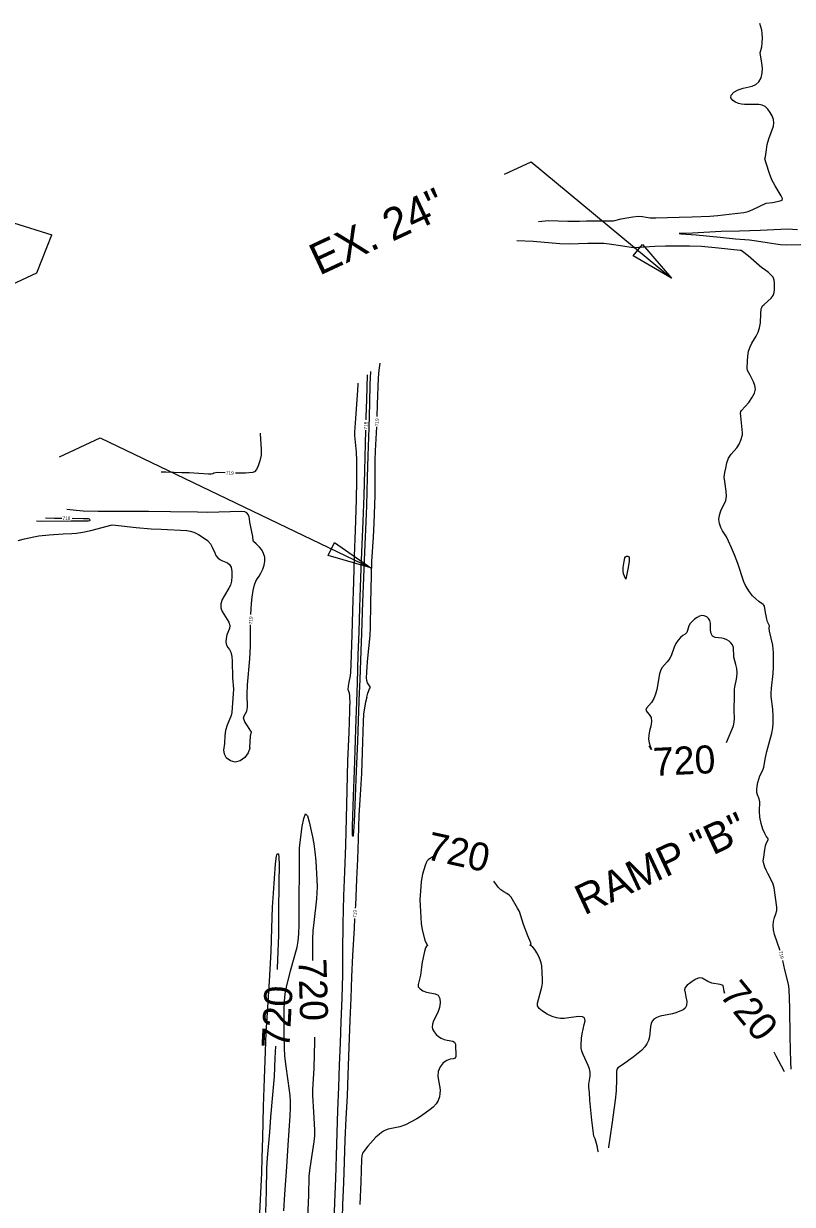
# Model space of a CAD drawing. Extents: x -310467766 to 17062430, y -322263100 to 8322522.
# Drawn here: x 1394051 to 1394957, y 571443 to 572834 of the extents above; entities that cross this region are included whole.
import ezdxf

# ---------------------------------------------------------------- set-up
doc = ezdxf.new("R2010")
doc.units = 0
for name, color, linetype in [('DT_X_Contour_Minor', 7, 'Continuous'), ('Level 19', 7, 'Continuous'), ('Level 40', 7, 'Continuous')]:
    doc.layers.add(name, color=color, linetype=linetype)

msp = doc.modelspace()

# ---------------------------------------------------------------- linework, layer by layer
at = {"layer": 'DT_X_Contour_Minor'}
for points in [[(1394657.8, 572601.2), (1394669.5, 572602.2), (1394692.3, 572601.7), (1394706.2, 572601.6), (1394714.5, 572602), (1394746.1, 572602.1), (1394755.2, 572604.3), (1394761.8, 572605.6), (1394769.1, 572606.8), (1394775.7, 572607.4), (1394780.5, 572607.1), (1394784.5, 572606.2), (1394789.3, 572605.5), (1394796, 572605.4), (1394823.4, 572606.3), (1394838.9, 572606.6), (1394859.8, 572607.4), (1394869.1, 572608.3), (1394889, 572610.6), (1394899.8, 572611.7), (1394904.9, 572613), (1394910.5, 572615.2), (1394926, 572622.6), (1394933.6, 572623.7), (1394942.7, 572625.3), (1394945, 572626.3), (1394945.4, 572628.2), (1394943.9, 572631.5), (1394936.8, 572643), (1394932.9, 572650.4), (1394929.8, 572657.8), (1394926, 572669.8), (1394924.6, 572674.9), (1394925.1, 572677.4), (1394926.3, 572685.6), (1394927.4, 572692), (1394929.1, 572698.5), (1394934.6, 572713.4), (1394935.1, 572717.4), (1394934.6, 572721.4), (1394933.2, 572725.4), (1394930.9, 572729.6), (1394928, 572733.5), (1394924.8, 572736.5), (1394921.3, 572738.1), (1394917.6, 572738.8), (1394909.3, 572739), (1394900.7, 572739.1), (1394896.8, 572739.4), (1394893.3, 572740.1), (1394889.9, 572741.5), (1394886.6, 572743.7), (1394884.5, 572746.7), (1394884.7, 572750), (1394887.8, 572753.3), (1394893.1, 572756.1), (1394899.1, 572758.3), (1394909.7, 572760.6), (1394914, 572762.4), (1394917.5, 572765.7), (1394920, 572770.3), (1394921.4, 572775.8), (1394921.6, 572781.8), (1394921.1, 572787.6), (1394918.9, 572799.8), (1394920.8, 572806.8), (1394921.3, 572811.7), (1394921.6, 572817.4), (1394921.4, 572822.6), (1394920.8, 572826.5), (1394918.6, 572834.2)], [(1394962.9, 572591.4), (1394951.1, 572591.9), (1394943.2, 572591.6), (1394919, 572590.5), (1394894.5, 572589.8), (1394873.2, 572589.2), (1394839.1, 572587.4), (1394823.7, 572586.8), (1394825.4, 572586.6), (1394843.6, 572585.4), (1394871.7, 572582.5), (1394889.9, 572580.8), (1394906.4, 572579.4), (1394914.8, 572578.5), (1394927.2, 572576.4), (1394937.3, 572574.7), (1394943.1, 572574.1), (1394950.1, 572573.8), (1394967, 572573.9)], [(1394881.6, 572224.6), (1394879.2, 572229.8), (1394874.6, 572236.8), (1394872.6, 572240.6), (1394870.9, 572245.2), (1394870.2, 572250.2), (1394870.9, 572255.3), (1394872.6, 572260.2), (1394878.5, 572272.6), (1394879.3, 572277.4), (1394879.1, 572283.4), (1394877.3, 572294.8), (1394876.4, 572300.1), (1394877.5, 572305.6), (1394878.4, 572310.7), (1394879.7, 572316.8), (1394881.8, 572322.5), (1394884.7, 572326.9), (1394891.3, 572334.4), (1394894.1, 572338.9), (1394896.2, 572343.5), (1394898.2, 572349.9), (1394898.3, 572352.1), (1394896.1, 572371.7), (1394896, 572375.2), (1394896.3, 572377.2), (1394896.9, 572378.4), (1394905.5, 572388.1), (1394909.3, 572393.4), (1394912.2, 572398.9), (1394913.3, 572403.7), (1394912.8, 572408.1), (1394911.3, 572412.2), (1394907, 572420.2), (1394904.2, 572425.8), (1394903.8, 572428.2), (1394903.9, 572436.5), (1394904.4, 572442.5), (1394905.4, 572448.3), (1394907.1, 572453.4), (1394909.2, 572457.7), (1394914.2, 572466.1), (1394916.5, 572470.8), (1394918.3, 572476), (1394919.3, 572481.8), (1394919.8, 572492.3), (1394920.1, 572498.2), (1394920.8, 572499.9), (1394921.9, 572501.6), (1394923.7, 572503.4), (1394932, 572510.9), (1394934.4, 572514.1), (1394935.6, 572517.6), (1394936, 572521.2), (1394935.9, 572528.6), (1394935.4, 572532.1), (1394934.1, 572535.4), (1394931.7, 572538.4), (1394928.9, 572541), (1394924, 572544.4), (1394921, 572546.4), (1394917.8, 572549.1), (1394905, 572560.6), (1394898.3, 572565.9), (1394896.5, 572566.9), (1394895.4, 572567.1), (1394869.7, 572569.7), (1394850, 572571.5), (1394835.6, 572571.9), (1394807.5, 572572.2), (1394795, 572571.6), (1394769.4, 572570), (1394757.2, 572572), (1394741.2, 572574.4), (1394735, 572575.1), (1394729.5, 572575.4), (1394715.9, 572575.1), (1394694.1, 572574.4), (1394682.8, 572575), (1394651.7, 572577.5), (1394632.4, 572578.4)], [(1394467.7, 572371.3), (1394468.2, 572385.7), (1394469.3, 572416.9), (1394470.1, 572425.9), (1394471.3, 572434.2)], [(1394446.8, 572037.2), (1394447.9, 572061.8), (1394448.9, 572095.4), (1394449.7, 572116.3), (1394450.8, 572152.6), (1394452, 572181.9), (1394453.2, 572211.6), (1394454.9, 572247.3), (1394455.6, 572266.4), (1394456.5, 572299.5), (1394457.2, 572324.9), (1394458.4, 572358.1), (1394459, 572387.3), (1394459.7, 572409.7), (1394460.4, 572424.5)], [(1394456.2, 572420.7), (1394455.2, 572391.6), (1394454.5, 572370.7), (1394454.4, 572367.4)], [(1394444.9, 572410.6), (1394444.9, 572408.6), (1394444.3, 572396.6), (1394442, 572364.1), (1394441.1, 572352.8), (1394441.2, 572349), (1394443.2, 572329.6), (1394443.5, 572319.7), (1394443.6, 572295.9), (1394442.9, 572273.6), (1394441.8, 572237.3), (1394440.8, 572207.2), (1394439.8, 572176.7), (1394438.6, 572143.1), (1394437.8, 572114.3), (1394436.9, 572079.2), (1394436.4, 572070.4), (1394435.9, 572065.8), (1394434.5, 572058.6), (1394433.5, 572053.6), (1394433.3, 572050), (1394433.7, 572049), (1394434.2, 572047.9), (1394434.8, 572045.9), (1394435.4, 572042.5), (1394435.6, 572032.3)], [(1394455.5, 572040.9), (1394456.9, 572045.6), (1394458.9, 572050.7), (1394459.8, 572052.3), (1394459.7, 572052.9), (1394456.6, 572057.7), (1394455.6, 572060.5), (1394455.2, 572063.5), (1394455.5, 572069.8), (1394456.5, 572082.9), (1394459.6, 572113.4), (1394459.9, 572122.9), (1394460.2, 572152.1), (1394461, 572184.1), (1394461.7, 572200.8), (1394463.5, 572229.4), (1394464.3, 572245.9), (1394465.5, 572278.5), (1394465.6, 572288.4), (1394465.6, 572320), (1394466, 572330.8), (1394467.3, 572359.3)], [(1394329.8, 572351.7), (1394330.3, 572344.4), (1394330.9, 572339.1), (1394331.3, 572332.7), (1394331.1, 572325.8), (1394329.7, 572319.1), (1394327.7, 572313.2), (1394325.5, 572308.8), (1394323.4, 572306.3), (1394320.9, 572305.3), (1394312.6, 572304.8), (1394300.9, 572304.7)], [(1394454.1, 572355.4), (1394453.7, 572339.3), (1394452.8, 572308), (1394452, 572278.2), (1394450.9, 572247.8), (1394449.5, 572211.8), (1394448.3, 572181.6), (1394447, 572146.4), (1394446.1, 572117.9), (1394445.2, 572090.6), (1394444.2, 572057.3), (1394443.6, 572035.8)], [(1394288.9, 572305), (1394279.6, 572305.3), (1394275.5, 572304.5), (1394274.1, 572304), (1394272.2, 572303.6), (1394269, 572303.6), (1394246.2, 572305), (1394237.8, 572305.1), (1394218.8, 572305.8), (1394213.5, 572305.9)], [(1394319, 572138), (1394319.2, 572144.9), (1394319.7, 572151), (1394320.6, 572158.5), (1394321.9, 572166.5), (1394323.4, 572173.2), (1394325, 572177.6), (1394326.7, 572180.6), (1394328.7, 572183.4), (1394330.9, 572187), (1394333.1, 572191.4), (1394334.7, 572196.2), (1394335.5, 572201), (1394335.4, 572205.6), (1394334.1, 572210.1), (1394331.9, 572214.2), (1394329.2, 572217.6), (1394325.4, 572221.5), (1394322.3, 572224), (1394321.8, 572224.9), (1394321.4, 572229.9), (1394317.9, 572246.8), (1394317.6, 572250.9), (1394317.1, 572253.3), (1394316, 572255.8), (1394314.4, 572257.8), (1394311.8, 572259), (1394308, 572259.5), (1394294.8, 572259.3), (1394268.1, 572258.5), (1394256.3, 572258.6), (1394224.5, 572259.2), (1394198.4, 572259.5), (1394166.6, 572259.6), (1394139.1, 572259.7), (1394121.6, 572260), (1394113.3, 572260.6), (1394102.1, 572261.9)], [(1394108.5, 572251.5), (1394122, 572251.4), (1394127.5, 572251.2), (1394128.5, 572250.8), (1394129.1, 572250.3), (1394129.3, 572249), (1394129, 572248.4), (1394127.4, 572248.3), (1394107.4, 572248.2), (1394072.9, 572247.9), (1394066.7, 572248)], [(1394077, 572252.1), (1394087.6, 572251.8), (1394096.5, 572251.7)], [(1394063.2, 572229.6), (1394069.3, 572230.7), (1394081.4, 572232.1), (1394097.9, 572233.1), (1394108, 572233.5), (1394113.7, 572233.9), (1394121.1, 572235.1), (1394130.5, 572237.3), (1394155.6, 572243.7), (1394159.7, 572243.4), (1394184, 572240.8), (1394201.5, 572239.2), (1394213.2, 572238.7), (1394243.6, 572237), (1394247.7, 572236.4), (1394251.9, 572235), (1394257.2, 572232.4), (1394263, 572229), (1394268.1, 572225.2), (1394271.5, 572221.4), (1394273.6, 572217.7), (1394276.4, 572210.7), (1394277.9, 572207.6), (1394280, 572205), (1394282.6, 572202.9), (1394285.6, 572201.4), (1394291.6, 572199), (1394294, 572197.2), (1394295.8, 572193.9), (1394296.7, 572188.9), (1394296.8, 572182.9), (1394296.2, 572177.3), (1394295, 572172.9), (1394293.2, 572169.1), (1394287.8, 572160.7), (1394285.1, 572155.7), (1394283.5, 572150.7), (1394283.7, 572146), (1394285.4, 572141.7), (1394293, 572129.3), (1394294.2, 572125.4), (1394293.8, 572121.7), (1394290.9, 572114.1), (1394289.9, 572109.8), (1394289.6, 572105.5), (1394290.3, 572102), (1394291.9, 572099.4), (1394293.9, 572097.1), (1394295.6, 572093.8), (1394296.7, 572088.8), (1394297.1, 572083.1), (1394297.5, 572063.7), (1394298.5, 572050.4), (1394298.2, 572044.8), (1394297, 572028.5), (1394296.7, 572022.6), (1394295.7, 572019.3), (1394291.1, 572007.9), (1394289.1, 572001.4), (1394288.4, 571995.6), (1394288.1, 571986.2), (1394286.9, 571978.3), (1394287.6, 571974.1), (1394289.9, 571969.5)], [(1394044.8, 572225.4), (1394052.4, 572227.3), (1394063.2, 572229.6)], [(1394942.4, 571742.4), (1394942.2, 571743), (1394935.9, 571761.1), (1394934.6, 571766.8), (1394934.2, 571771.9), (1394934.6, 571776.7), (1394935.9, 571781.3), (1394937.5, 571785.7), (1394938.6, 571789.7), (1394938.8, 571793.4), (1394935.4, 571816.2), (1394934.1, 571820.6), (1394932.4, 571824.9), (1394927.9, 571833.2), (1394925.9, 571837), (1394924.4, 571840.6), (1394922.8, 571846.1), (1394922.7, 571847.9), (1394923.1, 571852.5), (1394924.4, 571861.3), (1394925.2, 571865.5), (1394926.2, 571868.4), (1394928.4, 571872.7), (1394928.5, 571873.8), (1394928.2, 571874.7), (1394926.1, 571877), (1394924.3, 571880.1), (1394922.1, 571885.3), (1394920, 571892.1), (1394918.6, 571899.4), (1394918.2, 571906.4), (1394918.5, 571917.4), (1394917.8, 571920.9), (1394915.7, 571925.8), (1394915.2, 571928.6), (1394915.1, 571932), (1394915.6, 571935.8), (1394916.3, 571940.2), (1394917.4, 571944.4), (1394918.6, 571948), (1394922.1, 571954.8), (1394923.1, 571958.4), (1394925.4, 571969.9), (1394926.7, 571976.9), (1394932.8, 571998.6), (1394933.9, 572004.7), (1394934.3, 572009.9), (1394934.4, 572018.3), (1394933.8, 572026.5), (1394932.1, 572041.6), (1394931.9, 572045.2), (1394932.5, 572051.6), (1394934.4, 572068.5), (1394934.8, 572076), (1394934.6, 572093.4), (1394934.4, 572097.4), (1394933.7, 572102), (1394929.8, 572118.7), (1394929.7, 572121.9), (1394930.1, 572124.9), (1394929.6, 572125.8), (1394928.7, 572127.2), (1394927.7, 572129.4), (1394926.7, 572132.7), (1394925.3, 572140.5), (1394924, 572148), (1394923.4, 572149.1), (1394922.4, 572150.1), (1394917.5, 572153.5), (1394913.8, 572156.5), (1394910, 572160.3), (1394906.5, 572164.7), (1394901.8, 572172.5), (1394899.8, 572176.6), (1394892.6, 572198.1), (1394888.9, 572208.4), (1394885.2, 572216.7), (1394881.6, 572224.6)], [(1394760.9, 572179.8), (1394759.1, 572183.3), (1394758, 572186.2), (1394757.4, 572189.7), (1394757.4, 572193.5), (1394758.6, 572200.6), (1394759.5, 572205), (1394760.2, 572206.2), (1394761.4, 572206.9), (1394762.7, 572207), (1394763.9, 572206.4), (1394764.6, 572205.3), (1394764.8, 572203.8), (1394764.6, 572200.6), (1394762.9, 572191.4), (1394760.9, 572179.8)], [(1394879.5, 571987.3), (1394887.5, 572007.1), (1394888.4, 572011.2), (1394888.6, 572015.5), (1394888.3, 572025), (1394888.7, 572042.7), (1394888.6, 572049.7), (1394889.1, 572052.9), (1394890.9, 572060), (1394891.6, 572064.5), (1394891.9, 572069.5), (1394891.6, 572074.5), (1394890.5, 572079.2), (1394888.1, 572088), (1394887.8, 572092), (1394887.7, 572095.8), (1394887.4, 572099.3), (1394886.3, 572102.3), (1394884.5, 572104.8), (1394882.3, 572106.9), (1394879.9, 572108.5), (1394877.1, 572109.7), (1394873.8, 572110.4), (1394865.8, 572111.2), (1394862.7, 572112.8), (1394861.2, 572115.8), (1394860.6, 572119.9), (1394860.3, 572127.9), (1394859.6, 572131.1), (1394858.2, 572133.6), (1394856, 572135.5), (1394853.2, 572136.7), (1394850.2, 572137), (1394847.4, 572136.3), (1394844.6, 572134.8), (1394841.8, 572132.7), (1394839.1, 572130.3), (1394836.7, 572127.7), (1394835, 572124.8), (1394834.1, 572121.9), (1394833.5, 572119.2), (1394832.5, 572116.9), (1394830.6, 572115.1), (1394828, 572113.4), (1394825.1, 572111.2), (1394822.2, 572108.1), (1394819.6, 572104.2), (1394817.5, 572099.8), (1394814.5, 572090.7), (1394812.5, 572086.4), (1394809.5, 572082.4), (1394803.3, 572075.2), (1394801.5, 572071.9), (1394800.5, 572068.4), (1394797.4, 572049.8), (1394795.7, 572044.4), (1394793.6, 572039.2), (1394790.9, 572034.6), (1394785.1, 572027.9), (1394784.2, 572025.4), (1394785.7, 572023), (1394788.4, 572020.4), (1394790.6, 572016.8), (1394791, 572012.1), (1394790, 572006.5), (1394788.7, 572001), (1394787.8, 571995.9), (1394787.6, 571991.3), (1394788.1, 571987.1), (1394789.3, 571983), (1394791.1, 571979.2), (1394788.4, 571983.4)], [(1394318, 571981.6), (1394318.7, 571994.7), (1394319.6, 571999.8), (1394319.1, 572000.9), (1394314.9, 572007), (1394312, 572011.7), (1394310.4, 572016), (1394311, 572019), (1394312.8, 572021.5), (1394314.4, 572024.5), (1394314.9, 572029), (1394314.6, 572044.4), (1394315.1, 572055.5), (1394317.8, 572086.1), (1394318.5, 572101), (1394318.8, 572126)], [(1394455.5, 572040.9), (1394455.5, 572040.9), (1394454.1, 572034.9), (1394452.8, 572028.1), (1394451.9, 572020.6), (1394451.2, 572011.9), (1394450.4, 571988.1), (1394449.3, 571951), (1394447.6, 571925.8), (1394446.2, 571901.9), (1394445.4, 571873.7), (1394444.5, 571850.1), (1394443.6, 571826.3), (1394442.1, 571795.4), (1394441.9, 571792.2)], [(1394417.2, 571421.6), (1394417.9, 571446), (1394419.1, 571473.9), (1394420, 571500.4), (1394420.8, 571527.8), (1394421.6, 571553.8), (1394422.6, 571581.3), (1394423.5, 571607.5), (1394424.6, 571633.5), (1394425.5, 571658.5), (1394426.5, 571686.1), (1394427.2, 571713.9), (1394427.5, 571741.2), (1394427.9, 571773.8), (1394428.7, 571806.9), (1394429.8, 571835.1), (1394430.8, 571866.6), (1394431.7, 571898.4), (1394432.4, 571930.9), (1394433.1, 571965.8), (1394434.7, 571999.1), (1394435.6, 572024.3), (1394435.6, 572032.3)], [(1394443.6, 572035.8), (1394443.6, 572035.5), (1394442.4, 572003.4), (1394441.9, 571990), (1394440.6, 571954.1), (1394439.6, 571924.1), (1394438.4, 571888.7), (1394438.4, 571878.3), (1394438.8, 571877.6), (1394440.1, 571877.6), (1394441.1, 571893.8), (1394442.3, 571923.8), (1394443.6, 571953.5), (1394445.1, 571989.1), (1394446, 572013), (1394446.8, 572035.6), (1394446.8, 572037.2)], [(1394318, 571981.6), (1394318, 571980.9), (1394316, 571975.3), (1394312, 571969.9), (1394306.6, 571965.8), (1394300.6, 571964.2), (1394295, 571965.7), (1394290.1, 571969.3), (1394289.9, 571969.5)], [(1394357.9, 571435.9), (1394359.1, 571455.3), (1394361.4, 571487.5), (1394362.8, 571513.1), (1394365.5, 571547.8), (1394365.9, 571556.9), (1394365.8, 571564.4), (1394365.2, 571571.8), (1394362.8, 571589), (1394360.1, 571608.7), (1394359.1, 571618.5), (1394358.5, 571627.4), (1394358.3, 571642.4), (1394358.3, 571672.2), (1394358.7, 571682.6), (1394359.6, 571691.4), (1394361.1, 571699.4), (1394365.9, 571718.4), (1394373.5, 571746.5), (1394374.8, 571753.5), (1394375.6, 571761.9), (1394375.9, 571773.2), (1394376.1, 571805.9), (1394376.2, 571832.6), (1394376.2, 571855), (1394376.5, 571863), (1394377.1, 571869.9), (1394379.5, 571888.3), (1394381.3, 571898), (1394383.3, 571903.2), (1394385.6, 571901.1), (1394387.9, 571893.8), (1394391.8, 571876.2), (1394393.3, 571868), (1394394.5, 571858.7), (1394395.5, 571847.7), (1394396.8, 571825.5), (1394397, 571817.4), (1394396.8, 571810.5), (1394396.3, 571803.4), (1394393.1, 571775.2), (1394392.2, 571765.6), (1394391.7, 571755.9), (1394391.5, 571745.5), (1394391.7, 571730.6)], [(1394328.7, 571418.1), (1394330.2, 571448.8), (1394331.8, 571480.5), (1394332.5, 571498.6), (1394333, 571521.6), (1394334, 571558.5), (1394335.2, 571591.6), (1394336.2, 571623.6), (1394337.1, 571645.6), (1394339, 571675.5), (1394340.8, 571706.3), (1394342.8, 571741.2), (1394343.7, 571768.8), (1394344.6, 571793.4), (1394345.6, 571809.8), (1394348.2, 571844.3), (1394349.1, 571853.6), (1394349.5, 571855.2), (1394350, 571856.1), (1394351.1, 571856.4), (1394351.4, 571856.3), (1394351.7, 571855.8), (1394352, 571852.2), (1394352.2, 571843.5), (1394351.9, 571822.7), (1394351.7, 571787.4), (1394351.5, 571760.6), (1394350.8, 571741.3), (1394350, 571721.7), (1394349.9, 571719.9)], [(1394533.3, 571852.7), (1394528.2, 571849.6), (1394526.8, 571847.9), (1394525.5, 571845.5), (1394524.4, 571842.6), (1394521.4, 571832.5), (1394519.6, 571823.8), (1394518.8, 571812.4), (1394518.2, 571802.2), (1394518.5, 571795.4), (1394519.7, 571774.1), (1394521, 571766.7), (1394524.1, 571754.4), (1394525.9, 571750.2), (1394526.8, 571749), (1394527.1, 571748), (1394526.6, 571747.9), (1394525.8, 571747.4), (1394524.8, 571745.4), (1394523.6, 571741.4), (1394520.8, 571728.5), (1394519.9, 571722.7), (1394518.7, 571713.4), (1394517.7, 571708.7), (1394516, 571702.3), (1394516.3, 571699.7), (1394518.3, 571697.2), (1394521.7, 571694.9), (1394526.1, 571693.3), (1394536, 571691.5), (1394539.8, 571689.6), (1394541.8, 571685.9), (1394542.2, 571680.8), (1394541.1, 571675.1), (1394539.1, 571669.4), (1394534.3, 571659.4), (1394532.9, 571655.7), (1394532.5, 571652.6), (1394533.1, 571649.6), (1394534.8, 571646.6), (1394537.3, 571643.6), (1394540.2, 571641), (1394543.4, 571639), (1394546.7, 571637.7), (1394550.2, 571636.8), (1394556.8, 571635.6), (1394559, 571634.3), (1394559.9, 571631.9), (1394560.4, 571617.7), (1394559.6, 571615.5), (1394557.3, 571614.7), (1394553.9, 571614.3), (1394549.8, 571613), (1394545.6, 571609.9), (1394542, 571605.3), (1394539.7, 571599.9), (1394539.2, 571594.5), (1394539.9, 571589.3), (1394541.8, 571580.9), (1394542.1, 571577.5), (1394541.8, 571574), (1394541.1, 571570.1), (1394539.7, 571565.8), (1394537.3, 571561.7), (1394533.9, 571558), (1394530.2, 571555), (1394519.9, 571547.7), (1394514.6, 571544.3), (1394508, 571540.4), (1394501.1, 571537), (1394494.7, 571534.8), (1394480.8, 571531.9), (1394477.8, 571530.9), (1394475.2, 571529.6), (1394472.8, 571528.1), (1394470, 571525.8), (1394466.4, 571522.4), (1394456.9, 571511.9), (1394452.9, 571507), (1394450.6, 571503.5), (1394449.6, 571500.5), (1394449.4, 571496.7), (1394448.7, 571469.9), (1394447.3, 571443.1)], [(1394728.4, 571504.8), (1394728.3, 571505.8), (1394727.1, 571512.2), (1394724.6, 571520.4), (1394723.2, 571523.7), (1394720.7, 571542.5), (1394718.3, 571566.1), (1394718, 571575.3), (1394717.2, 571581.2), (1394717.3, 571585), (1394718.6, 571594.3), (1394718.8, 571599), (1394718, 571603.2), (1394716.5, 571607), (1394710.3, 571619.8), (1394708.8, 571623.9), (1394708.1, 571627.4), (1394708, 571630.8), (1394708.6, 571639.1), (1394709.3, 571644.4), (1394710.3, 571649.8), (1394711.7, 571655.1), (1394712.7, 571659.7), (1394712.1, 571662.9), (1394709.5, 571664.4), (1394705.3, 571664.6), (1394696.2, 571663.4), (1394687.9, 571662.4), (1394683.6, 571662.4), (1394679, 571663.1), (1394673.8, 571664.7), (1394668, 571667.4), (1394662.5, 571670.8), (1394658.5, 571674.2), (1394656.6, 571677.2), (1394656.6, 571680.3), (1394661.9, 571699.1), (1394662.5, 571703.9), (1394662.7, 571708.2), (1394662.3, 571716.6), (1394661.6, 571724.5), (1394660.9, 571728), (1394659.9, 571731.5), (1394658.2, 571735.3), (1394656, 571739.5), (1394653.4, 571743.5), (1394651.1, 571746.5), (1394649.4, 571747.8), (1394648.1, 571748.4), (1394649.1, 571750.2), (1394648.8, 571751.5), (1394645.4, 571759.8), (1394640.1, 571773.2), (1394635.3, 571788.3), (1394633.3, 571792.3), (1394625.6, 571805.2), (1394623.4, 571807.5), (1394620.4, 571809.4), (1394616.9, 571811.4), (1394613.3, 571813.9), (1394610.2, 571817.1), (1394605.2, 571824)], [(1394441.3, 571780.2), (1394440.6, 571768.8), (1394438.8, 571736.5), (1394437.6, 571711.2), (1394436.6, 571686.1), (1394435.6, 571660.3), (1394434.5, 571628.4), (1394433.3, 571595.9), (1394432.3, 571571.2), (1394431.1, 571544.6), (1394429.9, 571519.3), (1394429, 571493.4), (1394428, 571469.1), (1394427, 571442.7), (1394426, 571413), (1394425.1, 571395.6), (1394424.6, 571384.9), (1394423.7, 571373.5)], [(1394955.5, 571602.6), (1394955.1, 571610.8), (1394954.4, 571640.8), (1394953.8, 571674.3), (1394953.2, 571696.9), (1394952.2, 571702.6), (1394948.2, 571719.6), (1394945.5, 571730.8)], [(1394876.3, 571694.7), (1394877.1, 571692.1), (1394875.3, 571701.2), (1394874.3, 571701.7), (1394871.7, 571702.3), (1394862.1, 571704.1), (1394857.3, 571705.7), (1394850.8, 571709.7), (1394847.3, 571710.1), (1394842.5, 571708.2), (1394837.2, 571704.9), (1394832.9, 571701.5), (1394830.6, 571698.7), (1394830, 571696.1), (1394830.6, 571692.6), (1394831.6, 571687.8), (1394832.4, 571682.4), (1394832.3, 571677.8), (1394830.8, 571674.6), (1394828.3, 571672.7), (1394819.5, 571668.9), (1394815.8, 571667.8), (1394801.3, 571664.9), (1394797.2, 571663.4), (1394793.9, 571661.5), (1394791.7, 571659.1), (1394790.4, 571656.3), (1394789.7, 571653), (1394788.8, 571640.7), (1394787.6, 571636.4), (1394785.6, 571632.5), (1394783.2, 571629.1), (1394779.1, 571624.8), (1394769.3, 571616.7), (1394756.8, 571607.9), (1394751.5, 571604), (1394750.3, 571602.4), (1394749.8, 571600.3), (1394749.7, 571590.9), (1394749.4, 571577.1), (1394748.3, 571566), (1394744.2, 571537.3), (1394740.4, 571510.7), (1394740.3, 571509.9)], [(1394394, 571640.3), (1394394.1, 571635.8), (1394393.1, 571603.8), (1394392, 571584.5), (1394391.5, 571578.5), (1394391.5, 571571.8), (1394392.7, 571551.9), (1394394.1, 571531.2), (1394394, 571524), (1394393.2, 571516.9), (1394390.8, 571501.7), (1394388, 571483.3), (1394387.5, 571476.5), (1394387.1, 571453.7), (1394385.4, 571419.7), (1394385.6, 571413), (1394387.2, 571395.8), (1394389.4, 571375.4), (1394389.7, 571369.3), (1394389.9, 571363.3), (1394389.8, 571358.9)], [(1394347.9, 571629.9), (1394347.4, 571615.4), (1394346.3, 571594.1), (1394344.6, 571572.3), (1394342.3, 571546.1), (1394341, 571528.6), (1394338.1, 571498.1), (1394337.4, 571486), (1394336.9, 571458.9), (1394336.1, 571433.8)], [(1394947.8, 571599.3), (1394947.2, 571600.4), (1394937.7, 571618), (1394935.3, 571622.7)]]:
    msp.add_lwpolyline(points, dxfattribs=at)
at = {"layer": 'Level 40'}
for p, q in [((1394617.7, 572656.8), (1394649.3, 572671.5)), ((1394649.3, 572671.5), (1394814.5, 572534.4)), ((1394039.5, 572599.6), (1394084.7, 572585.5)), ((1394067, 572540.6), (1394084.7, 572585.5)), ((1394769.3, 572560.7), (1394780.3, 572573.9)), ((1394780.3, 572573.9), (1394814.5, 572534.4)), ((1394814.5, 572534.4), (1394769.3, 572560.7)), ((1393559.4, 572304), (1394067, 572540.6)), ((1394093.7, 572323.8), (1394141.6, 572346.1)), ((1394141.6, 572346.1), (1394460.5, 572193)), ((1394410.2, 572207.6), (1394417.7, 572223.1)), ((1394417.7, 572223.1), (1394460.5, 572193)), ((1394460.5, 572193), (1394410.2, 572207.6))]:
    msp.add_line(p, q, dxfattribs=at)

# ---------------------------------------------------------------- texts
at = {"layer": 'Level 19'}
for s, height, rotation, p in [('718', 4, 88.522, (1394456.1, 572356.1)), ('719', 4, 88.0522, (1394469.3, 572360)), ('719', 4, 358.2419, (1394289.6, 572303)), ('718', 4, 359.3935, (1394097.2, 572249.7)), ('719', 4, 88.7454, (1394320.8, 572126.7)), ('720', 33, 2.7101, (1394793.4, 571948)), ('720', 33, 347.5881, (1394524.1, 571850.3)), ('719', 4, 86.7401, (1394443.3, 571780.8)), ('719', 4, 283.7001, (1394940.9, 571741.3)), ('720', 33, 271.6966, (1394375, 571732.5)), ('720', 33, 309.4488, (1394870, 571689.7)), ('720', 33, 86.9578, (1394364.4, 571626.5))]:
    msp.add_text(s, height=height, rotation=rotation, dxfattribs=at).set_placement(p)
at = {"layer": 'Level 40'}
for s, height, p in [('EX. 24" ', 37.5, (1394399.7, 572537.1)), ('RAMP "B"', 35.5, (1394711.7, 571783.6))]:
    msp.add_text(s, height=height, rotation=25, dxfattribs=at).set_placement(p)

doc.saveas('drawing.dxf')
